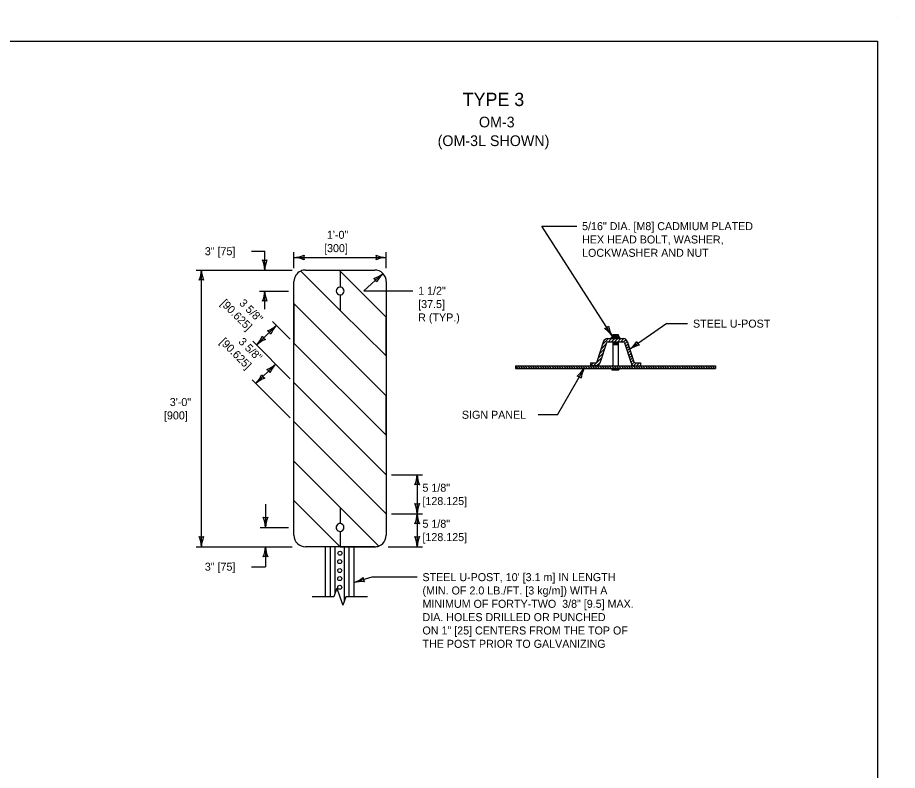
# Model space of a CAD drawing. Extents: x 49991.4 to 50021, y 49987.6 to 50011.4.
# Drawn here: x 50010.3 to 50016.9, y 49993.53 to 49999.18 of the extents above; entities that cross this region are included whole.
import ezdxf

# ---------------------------------------------------------------- set-up
doc = ezdxf.new("R2010")
doc.units = 0
for name, color, linetype in [('Level 1', 7, 'Continuous'), ('Level 2', 7, 'Continuous'), ('Level 3', 7, 'Continuous'), ('Level 6', 7, 'Continuous')]:
    doc.layers.add(name, color=color, linetype=linetype)

msp = doc.modelspace()

# ---------------------------------------------------------------- linework, layer by layer
at = {"layer": 'Level 1'}
for p, q in [((50016.9001, 49999.1756), (50016.9001, 49999.1756)), ((50012.7218, 49996.9799), (50012.427, 49997.2746)), ((50012.4624, 49997.2822), (50012.9813, 49997.2822)), ((50012.4625, 49997.2822), (50012.7148, 49997.2824)), ((50012.7148, 49997.2824), (50012.7223, 49997.2749)), ((50012.7223, 49997.2749), (50012.7223, 49997.1542)), ((50013.0678, 49996.9294), (50012.7223, 49997.2749)), ((50012.7223, 49997.2749), (50012.7223, 49997.1542)), ((50012.3761, 49995.2935), (50012.3761, 49997.1957)), ((50013.0678, 49997.1956), (50013.0678, 49995.2934)), ((50012.7223, 49997.0957), (50012.7225, 49996.9792)), ((50012.7223, 49997.0957), (50012.7225, 49996.9792)), ((50013.0678, 49996.3385), (50012.3761, 49997.0301)), ((50012.3761, 49997.0301), (50012.3761, 49997.0282)), ((50012.3761, 49997.0282), (50012.3761, 49996.7346)), ((50012.7225, 49996.9792), (50012.7218, 49996.9799)), ((50012.7225, 49996.9792), (50013.0678, 49996.6391)), ((50013.0678, 49996.6391), (50013.0678, 49996.9294)), ((50012.3761, 49996.7346), (50013.0678, 49996.0429)), ((50014.6974, 49996.7477), (50014.6479, 49996.5943)), ((50014.7184, 49996.7363), (50014.669, 49996.5829)), ((50014.6894, 49996.7229), (50014.7344, 49996.7679)), ((50014.7252, 49996.7679), (50014.8467, 49996.7679)), ((50014.7296, 49996.7444), (50014.8424, 49996.7444)), ((50014.7339, 49996.7444), (50014.7574, 49996.7679)), ((50014.7547, 49996.778), (50014.8173, 49996.778)), ((50014.7547, 49996.778), (50014.7547, 49996.7679)), ((50014.7571, 49996.7444), (50014.7806, 49996.7679)), ((50014.7606, 49996.789), (50014.8114, 49996.789)), ((50014.7606, 49996.789), (50014.7606, 49996.778)), ((50014.7664, 49996.7992), (50014.8055, 49996.7992)), ((50014.7664, 49996.7992), (50014.7664, 49996.789)), ((50014.7664, 49996.7444), (50014.7664, 49996.5627)), ((50014.7664, 49996.7341), (50014.8055, 49996.7341)), ((50014.7762, 49996.7941), (50014.7958, 49996.7941)), ((50014.7762, 49996.7393), (50014.7958, 49996.7393)), ((50014.7774, 49996.789), (50014.7774, 49996.778)), ((50014.7802, 49996.7444), (50014.8037, 49996.7679)), ((50014.7945, 49996.789), (50014.7945, 49996.778)), ((50014.8032, 49996.7444), (50014.8267, 49996.7679)), ((50014.8055, 49996.7992), (50014.8055, 49996.789)), ((50014.8055, 49996.7444), (50014.8055, 49996.5627)), ((50014.8114, 49996.789), (50014.8114, 49996.778)), ((50014.8173, 49996.778), (50014.8173, 49996.7679)), ((50014.8262, 49996.7444), (50014.8496, 49996.7678)), ((50014.8478, 49996.743), (50014.8657, 49996.7609)), ((50014.8535, 49996.7363), (50014.903, 49996.583)), ((50014.8561, 49996.7281), (50014.8748, 49996.7468)), ((50014.8745, 49996.7477), (50014.924, 49996.5943)), ((50014.6674, 49996.6547), (50014.7039, 49996.6912)), ((50014.6785, 49996.689), (50014.7149, 49996.7254)), ((50014.7664, 49996.7239), (50014.8055, 49996.7239)), ((50014.7762, 49996.729), (50014.7958, 49996.729)), ((50014.8617, 49996.7107), (50014.8804, 49996.7294)), ((50014.8673, 49996.6933), (50014.886, 49996.712)), ((50014.873, 49996.676), (50014.8916, 49996.6946)), ((50014.8786, 49996.6584), (50014.8973, 49996.6771)), ((50014.6215, 49996.5627), (50014.6819, 49996.6231)), ((50014.6564, 49996.6206), (50014.6929, 49996.6571)), ((50014.8842, 49996.641), (50014.9029, 49996.6597)), ((50014.8899, 49996.6237), (50014.9085, 49996.6423)), ((50014.8955, 49996.6061), (50014.9142, 49996.6248)), ((50014.9011, 49996.5887), (50014.9198, 49996.6074)), ((50014.0359, 49996.5627), (50015.536, 49996.5627)), ((50014.0359, 49996.5627), (50014.0359, 49996.5451)), ((50014.0359, 49996.5627), (50014.0536, 49996.5451)), ((50014.0359, 49996.5451), (50015.536, 49996.5451)), ((50014.0539, 49996.5627), (50014.0716, 49996.5451)), ((50014.0719, 49996.5627), (50014.0896, 49996.5451)), ((50014.0899, 49996.5627), (50014.1076, 49996.5451)), ((50014.1079, 49996.5627), (50014.1256, 49996.5451)), ((50014.1259, 49996.5627), (50014.1436, 49996.5451)), ((50014.1439, 49996.5627), (50014.1616, 49996.5451)), ((50014.1619, 49996.5627), (50014.1796, 49996.5451)), ((50014.1799, 49996.5627), (50014.1976, 49996.5451)), ((50014.1979, 49996.5627), (50014.2156, 49996.5451)), ((50014.2159, 49996.5627), (50014.2336, 49996.5451)), ((50014.2339, 49996.5627), (50014.2516, 49996.5451)), ((50014.2519, 49996.5627), (50014.2696, 49996.5451)), ((50014.2699, 49996.5627), (50014.2876, 49996.5451)), ((50014.2879, 49996.5627), (50014.3056, 49996.5451)), ((50014.3059, 49996.5627), (50014.3236, 49996.5451)), ((50014.3239, 49996.5627), (50014.3416, 49996.5451)), ((50014.3419, 49996.5627), (50014.3596, 49996.5451)), ((50014.3599, 49996.5627), (50014.3776, 49996.5451)), ((50014.3779, 49996.5627), (50014.3956, 49996.5451)), ((50014.3959, 49996.5627), (50014.4136, 49996.5451)), ((50014.4139, 49996.5627), (50014.4316, 49996.5451)), ((50014.4319, 49996.5627), (50014.4496, 49996.5451)), ((50014.4499, 49996.5627), (50014.4676, 49996.5451)), ((50014.4679, 49996.5627), (50014.4856, 49996.5451)), ((50014.4859, 49996.5627), (50014.5036, 49996.5451)), ((50014.5039, 49996.5627), (50014.5216, 49996.5451)), ((50014.5219, 49996.5627), (50014.5396, 49996.5451)), ((50014.5399, 49996.5627), (50014.5576, 49996.5451)), ((50014.5579, 49996.5627), (50014.5756, 49996.5451)), ((50014.5759, 49996.5627), (50014.5936, 49996.5451)), ((50014.5939, 49996.5627), (50014.6116, 49996.5451)), ((50014.5984, 49996.5862), (50014.5984, 49996.5627)), ((50014.5984, 49996.5862), (50014.6368, 49996.5862)), ((50014.6411, 49996.5627), (50014.5984, 49996.5627)), ((50014.5985, 49996.5627), (50014.622, 49996.5862)), ((50014.6119, 49996.5627), (50014.6296, 49996.5451)), ((50014.6299, 49996.5627), (50014.6476, 49996.5451)), ((50014.6447, 49996.5629), (50014.671, 49996.5892)), ((50014.6479, 49996.5627), (50014.6656, 49996.5451)), ((50014.6659, 49996.5627), (50014.6836, 49996.5451)), ((50014.6839, 49996.5627), (50014.7016, 49996.5451)), ((50014.7019, 49996.5627), (50014.7196, 49996.5451)), ((50014.7199, 49996.5627), (50014.7376, 49996.5451)), ((50014.7379, 49996.5627), (50014.7556, 49996.5451)), ((50014.7559, 49996.5627), (50014.7736, 49996.5451)), ((50014.7592, 49996.5451), (50014.7592, 49996.5333)), ((50014.7739, 49996.5627), (50014.7916, 49996.5451)), ((50014.7773, 49996.5451), (50014.7773, 49996.5333)), ((50014.7919, 49996.5627), (50014.8096, 49996.5451)), ((50014.795, 49996.5451), (50014.795, 49996.5333)), ((50014.8099, 49996.5627), (50014.8276, 49996.5451)), ((50014.8106, 49996.5451), (50014.8106, 49996.5333)), ((50014.8279, 49996.5627), (50014.8456, 49996.5451)), ((50014.8459, 49996.5627), (50014.8636, 49996.5451)), ((50014.8639, 49996.5627), (50014.8816, 49996.5451)), ((50014.8819, 49996.5627), (50014.8996, 49996.5451)), ((50014.8999, 49996.5627), (50014.9176, 49996.5451)), ((50014.9085, 49996.5731), (50014.926, 49996.5906)), ((50014.9179, 49996.5627), (50014.9356, 49996.5451)), ((50014.9224, 49996.564), (50014.9446, 49996.5862)), ((50014.9308, 49996.5627), (50014.9735, 49996.5627)), ((50014.9352, 49996.5862), (50014.9735, 49996.5862)), ((50014.9359, 49996.5627), (50014.9536, 49996.5451)), ((50014.9443, 49996.5627), (50014.9678, 49996.5862)), ((50014.9539, 49996.5627), (50014.9716, 49996.5451)), ((50014.9673, 49996.5627), (50014.9735, 49996.5689)), ((50014.9719, 49996.5627), (50014.9896, 49996.5451)), ((50014.9735, 49996.5862), (50014.9735, 49996.5627)), ((50014.9899, 49996.5627), (50015.0076, 49996.5451)), ((50015.0079, 49996.5627), (50015.0256, 49996.5451)), ((50015.0259, 49996.5627), (50015.0436, 49996.5451)), ((50015.0439, 49996.5627), (50015.0616, 49996.5451)), ((50015.0619, 49996.5627), (50015.0796, 49996.5451)), ((50015.0799, 49996.5627), (50015.0976, 49996.5451)), ((50015.0979, 49996.5627), (50015.1156, 49996.5451)), ((50015.1159, 49996.5627), (50015.1336, 49996.5451)), ((50015.1339, 49996.5627), (50015.1516, 49996.5451)), ((50015.1519, 49996.5627), (50015.1696, 49996.5451)), ((50015.1699, 49996.5627), (50015.1876, 49996.5451)), ((50015.1879, 49996.5627), (50015.2056, 49996.5451)), ((50015.2059, 49996.5627), (50015.2236, 49996.5451)), ((50015.2239, 49996.5627), (50015.2416, 49996.5451)), ((50015.2419, 49996.5627), (50015.2596, 49996.5451)), ((50015.2599, 49996.5627), (50015.2776, 49996.5451)), ((50015.2779, 49996.5627), (50015.2956, 49996.5451)), ((50015.2959, 49996.5627), (50015.3136, 49996.5451)), ((50015.3139, 49996.5627), (50015.3316, 49996.5451)), ((50015.3319, 49996.5627), (50015.3496, 49996.5451)), ((50015.3499, 49996.5627), (50015.3676, 49996.5451)), ((50015.3679, 49996.5627), (50015.3856, 49996.5451)), ((50015.3859, 49996.5627), (50015.4036, 49996.5451)), ((50015.4039, 49996.5627), (50015.4216, 49996.5451)), ((50015.4219, 49996.5627), (50015.4396, 49996.5451)), ((50015.4399, 49996.5627), (50015.4576, 49996.5451)), ((50015.4579, 49996.5627), (50015.4756, 49996.5451)), ((50015.4759, 49996.5627), (50015.4936, 49996.5451)), ((50015.4939, 49996.5627), (50015.5116, 49996.5451)), ((50015.5119, 49996.5627), (50015.5296, 49996.5451)), ((50015.5299, 49996.5627), (50015.536, 49996.5566)), ((50015.536, 49996.5627), (50015.536, 49996.5451)), ((50014.7592, 49996.5333), (50014.8106, 49996.5333)), ((50012.3761, 49996.1452), (50012.3761, 49996.4393)), ((50012.3761, 49996.4393), (50013.0678, 49995.7472)), ((50013.0678, 49996.0429), (50013.0678, 49996.3385)), ((50013.0678, 49995.4544), (50012.3761, 49996.1452)), ((50012.3761, 49995.5527), (50012.3761, 49995.8482)), ((50012.3761, 49995.8482), (50012.7223, 49995.502)), ((50013.0678, 49995.7472), (50013.0678, 49995.4544)), ((50012.7213, 49995.207), (50012.3761, 49995.5527)), ((50012.7223, 49995.502), (50012.7223, 49995.3811)), ((50013.0121, 49995.2126), (50012.7223, 49995.502)), ((50012.7223, 49995.502), (50012.7223, 49995.5019)), ((50012.7223, 49995.5019), (50012.7223, 49995.3811)), ((50012.7223, 49995.3811), (50012.7223, 49995.3811)), ((50012.7218, 49995.3225), (50012.7213, 49995.207)), ((50012.7223, 49995.3224), (50012.7213, 49995.207)), ((50012.7223, 49995.3224), (50012.7213, 49995.207)), ((50012.9813, 49995.2069), (50012.4626, 49995.207)), ((50012.6137, 49994.8321), (50012.6137, 49995.207)), ((50012.6492, 49994.8321), (50012.6492, 49995.207)), ((50012.6846, 49994.8603), (50012.6846, 49995.207)), ((50012.7213, 49995.207), (50012.9809, 49995.2069)), ((50012.7555, 49994.8042), (50012.7555, 49995.2069)), ((50012.791, 49994.8321), (50012.791, 49995.2069)), ((50012.8263, 49994.8321), (50012.8263, 49995.2069))]:
    msp.add_line(p, q, dxfattribs=at)
msp.add_lwpolyline([(49999.3835, 49998.9992), (50016.7501, 49998.9992), (50016.7501, 49987.7988), (49999.3835, 49987.7988)], close=True, dxfattribs=at)
for centre in [(50012.7208, 49995.1586), (50012.7188, 49995.0956), (50012.7188, 49995.0288), (50012.7188, 49994.9677), (50012.7189, 49994.903)]:
    msp.add_circle(centre, 0.015, dxfattribs=at)
for centre, radius, start, end in [((50012.4626, 49997.1957), 0.0865, 114.24763, 180), ((50012.4625, 49997.1958), 0.0864, 90, 114.25288), ((50012.9813, 49997.1957), 0.0865, 359.92105, 90), ((50012.7226, 49997.125), 0.0293, 90.49172, 269.50828), ((50012.7226, 49997.125), 0.0293, 269.31841, 90.68159), ((50014.7252, 49996.7386), 0.0293, 90, 162.05403), ((50014.7296, 49996.7327), 0.0117, 90, 162.11105), ((50014.8423, 49996.7327), 0.0117, 17.88895, 90), ((50014.8467, 49996.7386), 0.0293, 18.01791, 90), ((50014.6367, 49996.5979), 0.0117, 270, 342.11094), ((50014.6412, 49996.592), 0.0293, 270, 342.11105), ((50014.9308, 49996.592), 0.0293, 197.88804, 270), ((50014.9352, 49996.5979), 0.0117, 197.88906, 270), ((50012.7218, 49995.3518), 0.0293, 89.02642, 269.99586), ((50012.7217, 49995.3517), 0.0294, 271.08372, 88.91628), ((50012.4626, 49995.2935), 0.0865, 180, 270), ((50012.9813, 49995.2934), 0.0865, 270, 0)]:
    msp.add_arc(centre, radius, start, end, dxfattribs=at)
msp.add_ellipse((50012.9809, 49995.2955), major_axis=(0, 0.0886), ratio=0.998717, start_param=3.141593, end_param=3.50192, dxfattribs=at)
at = {"layer": 'Level 3'}
for p, q in [((50014.7606, 49996.789), (50014.2332, 49997.6114)), ((50014.2332, 49997.6114), (50014.4962, 49997.6114)), ((50012.0588, 49997.4235), (50012.1571, 49997.4235)), ((50012.1571, 49997.2824), (50012.1571, 49997.4235)), ((50012.3761, 49997.2957), (50012.3761, 49997.4165)), ((50013.0678, 49997.2957), (50013.0678, 49997.4165)), ((50012.3761, 49997.3765), (50013.0678, 49997.3765)), ((50011.642, 49997.2824), (50012.3624, 49997.2824)), ((50011.682, 49995.2069), (50011.682, 49997.2824)), ((50013.0425, 49997.2568), (50012.9005, 49997.1269)), ((50012.1171, 49997.1249), (50012.3361, 49997.1249)), ((50012.1571, 49996.9876), (50012.1571, 49997.1249)), ((50012.9005, 49997.1269), (50013.2673, 49997.1269)), ((50012.0958, 49996.7196), (50012.2436, 49996.8672)), ((50012.3478, 49996.7629), (50012.2153, 49996.8955)), ((50015.1705, 49996.8804), (50014.8936, 49996.6885)), ((50015.1705, 49996.8804), (50015.3275, 49996.8804)), ((50012.3478, 49996.4676), (50012.0676, 49996.7479)), ((50012.238, 49996.5774), (50012.091, 49996.4305)), ((50014.3516, 49996.1969), (50014.5513, 49996.5451)), ((50012.3478, 49996.1734), (50012.0627, 49996.4587)), ((50014.3516, 49996.1969), (50014.2078, 49996.1969)), ((50013.1078, 49995.7473), (50013.3394, 49995.7473)), ((50013.2994, 49995.7473), (50013.2994, 49995.4519)), ((50012.163, 49995.5255), (50012.163, 49995.3521)), ((50013.1078, 49995.4544), (50013.3394, 49995.4544)), ((50013.2994, 49995.4519), (50013.2994, 49995.2069)), ((50012.123, 49995.3521), (50012.3361, 49995.3521)), ((50011.642, 49995.2069), (50012.3626, 49995.2069)), ((50012.163, 49995.2069), (50012.163, 49995.0575)), ((50013.0815, 49995.2069), (50013.3394, 49995.2069)), ((50012.0588, 49995.0575), (50012.163, 49995.0575)), ((50012.9596, 49994.9791), (50012.8263, 49994.9381)), ((50013.2995, 49994.9791), (50012.9596, 49994.9791))]:
    msp.add_line(p, q, dxfattribs=at)
for centre, radius, start, end in [((50012.1571, 49997.4106), 0.0548, 252.13882, 287.86118), ((50011.9244, 49997.2709), 0.233, 2.82731, 22.07716), ((50012.3792, 49997.2732), 0.2223, 157.45601, 177.63952), ((50012.3646, 49997.6092), 0.233, 272.82731, 292.07716), ((50012.3669, 49997.1544), 0.2223, 67.45601, 87.63952), ((50012.5043, 49997.3765), 0.0548, 162.13882, 197.86118), ((50013.077, 49997.5986), 0.2223, 247.45601, 267.63952), ((50012.9396, 49997.3765), 0.0548, 342.13882, 17.86118), ((50013.0793, 49997.1438), 0.233, 92.82731, 112.07716), ((50011.4599, 49997.2916), 0.2223, 337.45601, 357.63952), ((50011.9147, 49997.2939), 0.233, 182.82731, 202.07716), ((50011.682, 49997.1542), 0.0548, 72.13882, 107.86118), ((50012.8993, 49997.4269), 0.2223, 289.91171, 310.09521), ((50012.9479, 49997.1703), 0.0548, 24.59451, 60.31688), ((50013.2081, 49997.0929), 0.233, 135.28301, 154.53286), ((50011.935, 49997.1341), 0.2223, 337.45601, 357.63952), ((50012.3898, 49997.1364), 0.233, 182.82731, 202.07716), ((50012.1571, 49996.9967), 0.0548, 72.13882, 107.86118), ((50012.0931, 49997.0308), 0.2223, 292.41724, 312.60075), ((50012.4162, 49996.7106), 0.233, 137.78854, 157.03839), ((50012.1529, 49996.7766), 0.0548, 27.10005, 62.82241), ((50014.6914, 49996.8969), 0.0548, 284.81062, 320.53298), ((50014.5709, 49996.6537), 0.233, 35.49911, 54.74896), ((50014.9525, 49996.9012), 0.2223, 190.12781, 210.31132), ((50011.9233, 49996.8762), 0.233, 317.78854, 337.03839), ((50012.2463, 49996.556), 0.2223, 112.41724, 132.60075), ((50012.1866, 49996.8102), 0.0548, 207.10005, 242.82241), ((50014.7516, 49996.8732), 0.233, 307.54193, 326.79178), ((50014.999, 49996.7615), 0.0548, 196.85344, 232.5758), ((50015.0126, 49996.5007), 0.2223, 102.17063, 122.35414), ((50012.0875, 49996.741), 0.2223, 292.43657, 312.62008), ((50012.4106, 49996.4209), 0.233, 137.80787, 157.05772), ((50014.3632, 49996.6636), 0.2223, 307.62011, 327.80361), ((50014.7589, 49996.4393), 0.233, 152.99141, 172.24126), ((50011.9183, 49996.5869), 0.233, 317.80787, 337.05772), ((50012.2415, 49996.2669), 0.2223, 112.43657, 132.62008), ((50012.1816, 49996.5211), 0.0548, 207.11938, 242.84174), ((50012.1473, 49996.4868), 0.0548, 27.11938, 62.84174), ((50014.4875, 49996.4339), 0.0548, 42.30291, 78.02527), ((50013.0773, 49995.7565), 0.2223, 337.45601, 357.63952), ((50013.5321, 49995.7588), 0.233, 182.82731, 202.07716), ((50013.2994, 49995.6191), 0.0548, 72.13882, 107.86118), ((50013.2994, 49995.5826), 0.0548, 252.13882, 287.86118), ((50013.0667, 49995.4429), 0.233, 2.82731, 22.07716), ((50013.5215, 49995.4452), 0.2223, 157.45601, 177.63952), ((50012.163, 49995.4803), 0.0548, 252.13882, 287.86118), ((50011.9303, 49995.3406), 0.233, 2.82731, 22.07716), ((50012.3851, 49995.3429), 0.2223, 157.45601, 177.63952), ((50013.0773, 49995.4636), 0.2223, 337.45601, 357.63952), ((50013.5321, 49995.4659), 0.233, 182.82731, 202.07716), ((50013.2994, 49995.3262), 0.0548, 72.13882, 107.86118), ((50011.682, 49995.3351), 0.0548, 252.13882, 287.86118), ((50011.4493, 49995.1954), 0.233, 2.82731, 22.07716), ((50011.9041, 49995.1977), 0.2223, 157.45601, 177.63952), ((50013.2994, 49995.3351), 0.0548, 252.13882, 287.86118), ((50013.0667, 49995.1954), 0.233, 2.82731, 22.07716), ((50013.5215, 49995.1977), 0.2223, 157.45601, 177.63952), ((50011.9409, 49995.2161), 0.2223, 337.45601, 357.63952), ((50012.3957, 49995.2184), 0.233, 182.82731, 202.07716), ((50012.163, 49995.0787), 0.0548, 72.13882, 107.86118), ((50012.7469, 49995.1572), 0.233, 289.924, 309.17385), ((50012.9488, 49994.9758), 0.0548, 179.23551, 214.95787), ((50012.8829, 49994.7231), 0.2223, 84.5527, 104.73621)]:
    msp.add_arc(centre, radius, start, end, dxfattribs=at)
at = {"layer": 'Level 6'}
for p, q in [((50012.6973, 49994.8961), (50012.6746, 49994.8321)), ((50012.6973, 49994.8961), (50012.72, 49994.8321)), ((50012.6746, 49994.8321), (50012.5137, 49994.8321)), ((50012.72, 49994.8321), (50012.7427, 49994.7681)), ((50012.7654, 49994.8321), (50012.7427, 49994.7681)), ((50012.9263, 49994.8321), (50012.7654, 49994.8321))]:
    msp.add_line(p, q, dxfattribs=at)

# ---------------------------------------------------------------- texts
at = {"layer": 'Level 2'}
for s, height, p in [('TYPE 3', 0.1, (50013.6414, 49998.5121)), ('OM-3', 0.08, (50013.7627, 49998.3521)), ('(OM-3L SHOWN)', 0.08, (50013.4532, 49998.2121)), ('5/16" DIA. [M8] CADMIUM PLATED', 0.06, (50014.5362, 49997.5814)), ('HEX HEAD BOLT, WASHER,', 0.06, (50014.5362, 49997.4814)), ('3" [75]', 0.06, (50011.7077, 49997.3935)), ('LOCKWASHER AND NUT', 0.06, (50014.5362, 49997.3814)), ('1 1/2"', 0.06, (50013.3073, 49997.0969)), ('[37.5]', 0.06, (50013.3073, 49996.9969)), ('R (TYP.)', 0.06, (50013.3073, 49996.8969)), ('STEEL U-POST', 0.06, (50015.3675, 49996.8504)), ('SIGN PANEL', 0.06, (50013.635, 49996.1669)), ('3" [75]', 0.06, (50011.7077, 49995.0275)), ("STEEL U-POST, 10' [3.1 m] IN LENGTH", 0.06, (50013.3395, 49994.9491)), ('(MIN. OF 2.0 LB./FT. [3 kg/m]) WITH A', 0.06, (50013.3395, 49994.8491)), ('MINIMUM OF FORTY-TWO  3/8" [9.5] MAX.', 0.06, (50013.3395, 49994.7491)), ('DIA. HOLES DRILLED OR PUNCHED', 0.06, (50013.3395, 49994.6491)), ('ON 1" [25] CENTERS FROM THE TOP OF', 0.06, (50013.3395, 49994.5491)), ('THE POST PRIOR TO GALVANIZING', 0.06, (50013.3395, 49994.4491))]:
    msp.add_text(s, height=height, dxfattribs=at).set_placement(p)
for s, rotation, p in [('1\'-0"', 0.07052, (50012.6235, 49997.5164)), ('[300]', 0.07052, (50012.6019, 49997.4164)), ('[90.625]', 315.04388, (50011.8215, 49997.0276)), ('3 5/8"', 315.04388, (50011.9613, 49997.0293)), ('[90.625]', 315.02925, (50011.816, 49996.7379)), ('3 5/8"', 315.02925, (50011.9558, 49996.7396)), ('3\'-0"', 0.02928, (50011.4451, 49996.2621)), ('[900]', 0.02928, (50011.4017, 49996.1621)), ('5 1/8"', 0.04702, (50013.3394, 49995.6196)), ('[128.125]', 0.04702, (50013.3394, 49995.5196)), ('5 1/8"', 0.0235, (50013.3394, 49995.3494)), ('[128.125]', 0.0235, (50013.3394, 49995.2494))]:
    msp.add_text(s, height=0.06, rotation=rotation, dxfattribs=at).set_placement(p)

doc.saveas('drawing.dxf')
